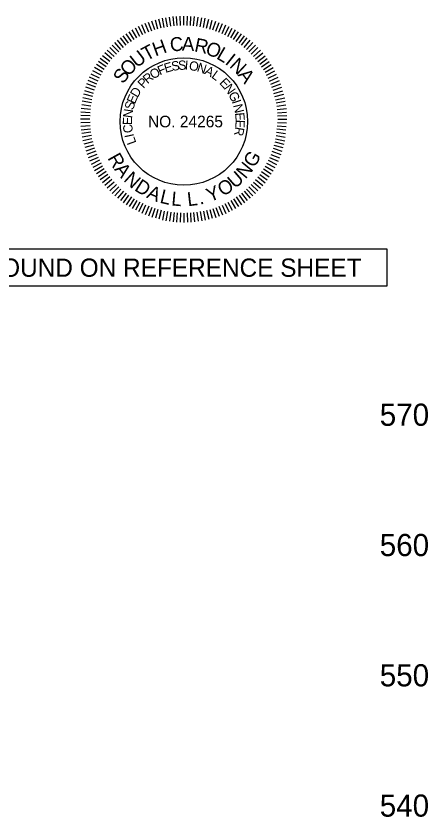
# Model space of a CAD drawing. Extents: x 1964849 to 1967422, y 1116563 to 1122210.
# Drawn here: x 1967263.8 to 1967421.9, y 1120325.5 to 1120632.8 of the extents above; entities that cross this region are included whole.
import ezdxf

# ---------------------------------------------------------------- set-up
doc = ezdxf.new("R2010")
doc.units = 0
for name, color, linetype in [('RD_DDB_Profile_Elev', 7, 'Continuous'), ('RD_Sketch1', 7, 'Continuous'), ('RD_TX_PEShield', 7, 'Continuous')]:
    doc.layers.add(name, color=color, linetype=linetype)

msp = doc.modelspace()

# ---------------------------------------------------------------- linework, layer by layer
at = {"layer": 'RD_Sketch1'}
msp.add_lwpolyline([(1967105.7, 1120543.48), (1967406.12, 1120543.48), (1967406.12, 1120529.22), (1967105.7, 1120529.22)], close=True, dxfattribs=at)
at = {"layer": 'RD_TX_PEShield'}
for p, q in [((1967324.46, 1120629.09), (1967324.09, 1120632.63)), ((1967324.46, 1120629.09), (1967324.09, 1120632.63)), ((1967325.71, 1120629.15), (1967325.47, 1120632.7)), ((1967325.71, 1120629.15), (1967325.47, 1120632.7)), ((1967326.97, 1120629.22), (1967326.84, 1120632.77)), ((1967326.97, 1120629.22), (1967326.84, 1120632.77)), ((1967328.23, 1120629.28), (1967328.23, 1120632.84)), ((1967328.23, 1120629.28), (1967328.23, 1120632.84)), ((1967329.48, 1120629.22), (1967329.61, 1120632.77)), ((1967329.48, 1120629.22), (1967329.61, 1120632.77)), ((1967330.74, 1120629.15), (1967330.98, 1120632.7)), ((1967330.74, 1120629.15), (1967330.98, 1120632.7)), ((1967331.99, 1120629.09), (1967332.36, 1120632.63)), ((1967331.99, 1120629.09), (1967332.36, 1120632.63)), ((1967314.74, 1120626.62), (1967313.41, 1120629.91)), ((1967314.74, 1120626.62), (1967313.41, 1120629.91)), ((1967315.91, 1120627.07), (1967314.7, 1120630.41)), ((1967315.91, 1120627.07), (1967314.7, 1120630.41)), ((1967317.09, 1120627.52), (1967315.99, 1120630.9)), ((1967317.09, 1120627.52), (1967315.99, 1120630.9)), ((1967318.3, 1120627.84), (1967317.32, 1120631.26)), ((1967318.3, 1120627.84), (1967317.32, 1120631.26)), ((1967319.52, 1120628.17), (1967318.66, 1120631.62)), ((1967319.52, 1120628.17), (1967318.66, 1120631.62)), ((1967320.73, 1120628.5), (1967319.99, 1120631.98)), ((1967320.73, 1120628.5), (1967319.99, 1120631.98)), ((1967321.97, 1120628.69), (1967321.36, 1120632.19)), ((1967321.97, 1120628.69), (1967321.36, 1120632.19)), ((1967323.21, 1120628.89), (1967322.72, 1120632.41)), ((1967323.21, 1120628.89), (1967322.72, 1120632.41)), ((1967333.24, 1120628.89), (1967333.73, 1120632.41)), ((1967333.24, 1120628.89), (1967333.73, 1120632.41)), ((1967334.48, 1120628.69), (1967335.09, 1120632.19)), ((1967334.48, 1120628.69), (1967335.09, 1120632.19)), ((1967335.72, 1120628.5), (1967336.46, 1120631.98)), ((1967335.72, 1120628.5), (1967336.46, 1120631.98)), ((1967335.72, 1120628.5), (1967336.46, 1120631.98)), ((1967336.93, 1120628.17), (1967337.79, 1120631.62)), ((1967336.93, 1120628.17), (1967337.79, 1120631.62)), ((1967336.93, 1120628.17), (1967337.79, 1120631.62)), ((1967338.15, 1120627.84), (1967339.13, 1120631.26)), ((1967338.15, 1120627.84), (1967339.13, 1120631.26)), ((1967338.15, 1120627.84), (1967339.13, 1120631.26)), ((1967339.36, 1120627.52), (1967340.46, 1120630.9)), ((1967339.36, 1120627.52), (1967340.46, 1120630.9)), ((1967339.36, 1120627.52), (1967340.46, 1120630.9)), ((1967340.54, 1120627.07), (1967341.75, 1120630.41)), ((1967340.54, 1120627.07), (1967341.75, 1120630.41)), ((1967340.54, 1120627.07), (1967341.75, 1120630.41)), ((1967341.71, 1120626.62), (1967343.04, 1120629.91)), ((1967341.71, 1120626.62), (1967343.04, 1120629.91)), ((1967341.71, 1120626.62), (1967343.04, 1120629.91)), ((1967309.15, 1120623.77), (1967307.26, 1120626.78)), ((1967309.15, 1120623.77), (1967307.26, 1120626.78)), ((1967310.2, 1120624.45), (1967308.42, 1120627.54)), ((1967310.2, 1120624.45), (1967308.42, 1120627.54)), ((1967311.32, 1120625.03), (1967309.65, 1120628.16)), ((1967311.32, 1120625.03), (1967309.65, 1120628.16)), ((1967312.44, 1120625.6), (1967310.88, 1120628.79)), ((1967312.44, 1120625.6), (1967310.88, 1120628.79)), ((1967313.56, 1120626.17), (1967312.12, 1120629.42)), ((1967313.56, 1120626.17), (1967312.12, 1120629.42)), ((1967342.89, 1120626.17), (1967344.33, 1120629.42)), ((1967342.89, 1120626.17), (1967344.33, 1120629.42)), ((1967342.89, 1120626.17), (1967344.33, 1120629.42)), ((1967344.01, 1120625.6), (1967345.57, 1120628.79)), ((1967344.01, 1120625.6), (1967345.57, 1120628.79)), ((1967344.01, 1120625.6), (1967345.57, 1120628.79)), ((1967345.13, 1120625.03), (1967346.8, 1120628.16)), ((1967345.13, 1120625.03), (1967346.8, 1120628.16)), ((1967345.13, 1120625.03), (1967346.8, 1120628.16)), ((1967346.25, 1120624.45), (1967348.03, 1120627.54)), ((1967346.25, 1120624.45), (1967348.03, 1120627.54)), ((1967346.25, 1120624.45), (1967348.03, 1120627.54)), ((1967347.3, 1120623.77), (1967349.19, 1120626.78)), ((1967347.3, 1120623.77), (1967349.19, 1120626.78)), ((1967347.3, 1120623.77), (1967349.19, 1120626.78)), ((1967305.08, 1120620.82), (1967302.8, 1120623.54)), ((1967305.08, 1120620.82), (1967302.8, 1120623.54)), ((1967306.06, 1120621.61), (1967303.87, 1120624.41)), ((1967306.06, 1120621.61), (1967303.87, 1120624.41)), ((1967307.04, 1120622.4), (1967304.95, 1120625.28)), ((1967307.04, 1120622.4), (1967304.95, 1120625.28)), ((1967308.09, 1120623.08), (1967306.11, 1120626.03)), ((1967308.09, 1120623.08), (1967306.11, 1120626.03)), ((1967348.36, 1120623.08), (1967350.34, 1120626.03)), ((1967348.36, 1120623.08), (1967350.34, 1120626.03)), ((1967348.36, 1120623.08), (1967350.34, 1120626.03)), ((1967349.41, 1120622.4), (1967351.5, 1120625.28)), ((1967349.41, 1120622.4), (1967351.5, 1120625.28)), ((1967349.41, 1120622.4), (1967351.5, 1120625.28)), ((1967350.39, 1120621.61), (1967352.58, 1120624.41)), ((1967350.39, 1120621.61), (1967352.58, 1120624.41)), ((1967350.39, 1120621.61), (1967352.58, 1120624.41)), ((1967351.37, 1120620.82), (1967353.65, 1120623.54)), ((1967351.37, 1120620.82), (1967353.65, 1120623.54)), ((1967351.37, 1120620.82), (1967353.65, 1120623.54)), ((1967302.33, 1120618.25), (1967299.77, 1120620.72)), ((1967302.33, 1120618.25), (1967299.77, 1120620.72)), ((1967303.22, 1120619.14), (1967300.75, 1120621.69)), ((1967303.22, 1120619.14), (1967300.75, 1120621.69)), ((1967304.11, 1120620.02), (1967301.72, 1120622.67)), ((1967304.11, 1120620.02), (1967301.72, 1120622.67)), ((1967352.34, 1120620.02), (1967354.73, 1120622.67)), ((1967352.34, 1120620.02), (1967354.73, 1120622.67)), ((1967352.34, 1120620.02), (1967354.73, 1120622.67)), ((1967353.23, 1120619.14), (1967355.7, 1120621.69)), ((1967353.23, 1120619.14), (1967355.7, 1120621.69)), ((1967353.23, 1120619.14), (1967355.7, 1120621.69)), ((1967354.12, 1120618.25), (1967356.68, 1120620.72)), ((1967354.12, 1120618.25), (1967356.68, 1120620.72)), ((1967354.12, 1120618.25), (1967356.68, 1120620.72)), ((1967299.86, 1120615.4), (1967297.05, 1120617.59)), ((1967299.86, 1120615.4), (1967297.05, 1120617.59)), ((1967300.65, 1120616.38), (1967297.92, 1120618.66)), ((1967300.65, 1120616.38), (1967297.92, 1120618.66)), ((1967301.44, 1120617.36), (1967298.79, 1120619.74)), ((1967301.44, 1120617.36), (1967298.79, 1120619.74)), ((1967355.01, 1120617.36), (1967357.66, 1120619.74)), ((1967355.01, 1120617.36), (1967357.66, 1120619.74)), ((1967355.01, 1120617.36), (1967357.66, 1120619.74)), ((1967355.8, 1120616.38), (1967358.53, 1120618.66)), ((1967355.8, 1120616.38), (1967358.53, 1120618.66)), ((1967355.8, 1120616.38), (1967358.53, 1120618.66)), ((1967356.59, 1120615.4), (1967359.4, 1120617.59)), ((1967356.59, 1120615.4), (1967359.4, 1120617.59)), ((1967356.59, 1120615.4), (1967359.4, 1120617.59)), ((1967297.69, 1120612.32), (1967294.68, 1120614.2)), ((1967297.69, 1120612.32), (1967294.68, 1120614.2)), ((1967298.38, 1120613.37), (1967295.43, 1120615.36)), ((1967298.38, 1120613.37), (1967295.43, 1120615.36)), ((1967299.06, 1120614.42), (1967296.18, 1120616.52)), ((1967299.06, 1120614.42), (1967296.18, 1120616.52)), ((1967357.39, 1120614.42), (1967360.27, 1120616.52)), ((1967357.39, 1120614.42), (1967360.27, 1120616.52)), ((1967357.39, 1120614.42), (1967360.27, 1120616.52)), ((1967358.07, 1120613.37), (1967361.02, 1120615.36)), ((1967358.07, 1120613.37), (1967361.02, 1120615.36)), ((1967358.07, 1120613.37), (1967361.02, 1120615.36)), ((1967358.76, 1120612.32), (1967361.77, 1120614.2)), ((1967358.76, 1120612.32), (1967361.77, 1120614.2)), ((1967358.76, 1120612.32), (1967361.77, 1120614.2)), ((1967296.44, 1120610.14), (1967293.3, 1120611.81)), ((1967296.44, 1120610.14), (1967293.3, 1120611.81)), ((1967297.01, 1120611.26), (1967293.93, 1120613.04)), ((1967297.01, 1120611.26), (1967293.93, 1120613.04)), ((1967359.44, 1120611.26), (1967362.52, 1120613.04)), ((1967359.44, 1120611.26), (1967362.52, 1120613.04)), ((1967359.44, 1120611.26), (1967362.52, 1120613.04)), ((1967360.01, 1120610.14), (1967363.15, 1120611.81)), ((1967360.01, 1120610.14), (1967363.15, 1120611.81)), ((1967360.01, 1120610.14), (1967363.15, 1120611.81)), ((1967294.85, 1120606.72), (1967291.55, 1120608.06)), ((1967294.85, 1120606.72), (1967291.55, 1120608.06)), ((1967295.3, 1120607.9), (1967292.04, 1120609.35)), ((1967295.3, 1120607.9), (1967292.04, 1120609.35)), ((1967295.87, 1120609.02), (1967292.67, 1120610.58)), ((1967295.87, 1120609.02), (1967292.67, 1120610.58)), ((1967360.58, 1120609.02), (1967363.78, 1120610.58)), ((1967360.58, 1120609.02), (1967363.78, 1120610.58)), ((1967360.58, 1120609.02), (1967363.78, 1120610.58)), ((1967361.15, 1120607.9), (1967364.41, 1120609.35)), ((1967361.15, 1120607.9), (1967364.41, 1120609.35)), ((1967361.15, 1120607.9), (1967364.41, 1120609.35)), ((1967361.6, 1120606.72), (1967364.9, 1120608.06)), ((1967361.6, 1120606.72), (1967364.9, 1120608.06)), ((1967361.6, 1120606.72), (1967364.9, 1120608.06)), ((1967293.94, 1120604.38), (1967290.56, 1120605.48)), ((1967293.94, 1120604.38), (1967290.56, 1120605.48)), ((1967294.4, 1120605.55), (1967291.05, 1120606.77)), ((1967294.4, 1120605.55), (1967291.05, 1120606.77)), ((1967362.06, 1120605.55), (1967365.4, 1120606.77)), ((1967362.06, 1120605.55), (1967365.4, 1120606.77)), ((1967362.06, 1120605.55), (1967365.4, 1120606.77)), ((1967362.51, 1120604.38), (1967365.89, 1120605.48)), ((1967362.51, 1120604.38), (1967365.89, 1120605.48)), ((1967362.51, 1120604.38), (1967365.89, 1120605.48)), ((1967293.29, 1120601.95), (1967289.84, 1120602.81)), ((1967293.29, 1120601.95), (1967289.84, 1120602.81)), ((1967293.62, 1120603.16), (1967290.2, 1120604.14)), ((1967293.62, 1120603.16), (1967290.2, 1120604.14)), ((1967362.83, 1120603.16), (1967366.25, 1120604.14)), ((1967362.83, 1120603.16), (1967366.25, 1120604.14)), ((1967362.83, 1120603.16), (1967366.25, 1120604.14)), ((1967363.16, 1120601.95), (1967366.61, 1120602.81)), ((1967363.16, 1120601.95), (1967366.61, 1120602.81)), ((1967363.16, 1120601.95), (1967366.61, 1120602.81)), ((1967292.57, 1120598.25), (1967289.05, 1120598.74)), ((1967292.57, 1120598.25), (1967289.05, 1120598.74)), ((1967292.77, 1120599.49), (1967289.27, 1120600.11)), ((1967292.77, 1120599.49), (1967289.27, 1120600.11)), ((1967292.97, 1120600.73), (1967289.49, 1120601.47)), ((1967292.97, 1120600.73), (1967289.49, 1120601.47)), ((1967363.48, 1120600.73), (1967366.96, 1120601.47)), ((1967363.48, 1120600.73), (1967366.96, 1120601.47)), ((1967363.48, 1120600.73), (1967366.96, 1120601.47)), ((1967363.68, 1120599.49), (1967367.18, 1120600.11)), ((1967363.68, 1120599.49), (1967367.18, 1120600.11)), ((1967363.68, 1120599.49), (1967367.18, 1120600.11)), ((1967363.88, 1120598.25), (1967367.4, 1120598.74)), ((1967363.88, 1120598.25), (1967367.4, 1120598.74)), ((1967363.88, 1120598.25), (1967367.4, 1120598.74)), ((1967292.31, 1120595.75), (1967288.76, 1120596)), ((1967292.31, 1120595.75), (1967288.76, 1120596)), ((1967292.38, 1120597.01), (1967288.84, 1120597.38)), ((1967292.38, 1120597.01), (1967288.84, 1120597.38)), ((1967364.07, 1120597.01), (1967367.61, 1120597.38)), ((1967364.07, 1120597.01), (1967367.61, 1120597.38)), ((1967364.07, 1120597.01), (1967367.61, 1120597.38)), ((1967364.14, 1120595.75), (1967367.69, 1120596)), ((1967364.14, 1120595.75), (1967367.69, 1120596)), ((1967364.14, 1120595.75), (1967367.69, 1120596)), ((1967292.18, 1120593.24), (1967288.62, 1120593.24)), ((1967292.18, 1120593.24), (1967288.62, 1120593.24)), ((1967292.25, 1120594.49), (1967288.69, 1120594.62)), ((1967292.25, 1120594.49), (1967288.69, 1120594.62)), ((1967364.2, 1120594.49), (1967367.76, 1120594.62)), ((1967364.2, 1120594.49), (1967367.76, 1120594.62)), ((1967364.2, 1120594.49), (1967367.76, 1120594.62)), ((1967364.27, 1120593.24), (1967367.83, 1120593.24)), ((1967364.27, 1120593.24), (1967367.83, 1120593.24)), ((1967364.27, 1120593.24), (1967367.83, 1120593.24)), ((1967292.25, 1120591.98), (1967288.69, 1120591.86)), ((1967292.25, 1120591.98), (1967288.69, 1120591.86)), ((1967292.31, 1120590.73), (1967288.76, 1120590.48)), ((1967292.31, 1120590.73), (1967288.76, 1120590.48)), ((1967292.38, 1120589.47), (1967288.84, 1120589.1)), ((1967292.38, 1120589.47), (1967288.84, 1120589.1)), ((1967363.88, 1120589.49), (1967367.4, 1120589.12)), ((1967363.88, 1120589.49), (1967367.4, 1120589.12)), ((1967364.01, 1120590.74), (1967367.54, 1120590.49)), ((1967364.01, 1120590.74), (1967367.54, 1120590.49)), ((1967364.14, 1120591.98), (1967367.69, 1120591.86)), ((1967364.14, 1120591.98), (1967367.69, 1120591.86)), ((1967292.57, 1120588.23), (1967289.05, 1120587.73)), ((1967292.57, 1120588.23), (1967289.05, 1120587.73)), ((1967292.77, 1120586.99), (1967289.27, 1120586.37)), ((1967292.77, 1120586.99), (1967289.27, 1120586.37)), ((1967363.61, 1120587), (1967367.11, 1120586.38)), ((1967363.61, 1120587), (1967367.11, 1120586.38)), ((1967363.75, 1120588.25), (1967367.25, 1120587.75)), ((1967363.75, 1120588.25), (1967367.25, 1120587.75)), ((1967292.97, 1120585.74), (1967289.49, 1120585)), ((1967292.97, 1120585.74), (1967289.49, 1120585)), ((1967293.29, 1120584.53), (1967289.84, 1120583.67)), ((1967293.29, 1120584.53), (1967289.84, 1120583.67)), ((1967363.16, 1120584.53), (1967366.61, 1120583.67)), ((1967363.16, 1120584.53), (1967366.61, 1120583.67)), ((1967363.48, 1120585.74), (1967366.96, 1120585)), ((1967363.48, 1120585.74), (1967366.96, 1120585)), ((1967293.62, 1120583.31), (1967290.2, 1120582.33)), ((1967293.62, 1120583.31), (1967290.2, 1120582.33)), ((1967293.94, 1120582.1), (1967290.56, 1120581)), ((1967294.4, 1120580.92), (1967291.05, 1120579.71)), ((1967294.4, 1120580.92), (1967291.05, 1120579.71)), ((1967362.06, 1120580.92), (1967365.4, 1120579.71)), ((1967362.06, 1120580.92), (1967365.4, 1120579.71)), ((1967362.51, 1120582.1), (1967365.89, 1120581)), ((1967362.51, 1120582.1), (1967365.89, 1120581)), ((1967362.83, 1120583.31), (1967366.25, 1120582.33)), ((1967362.83, 1120583.31), (1967366.25, 1120582.33)), ((1967294.85, 1120579.75), (1967291.55, 1120578.42)), ((1967294.85, 1120579.75), (1967291.55, 1120578.42)), ((1967295.3, 1120578.58), (1967292.04, 1120577.13)), ((1967295.3, 1120578.58), (1967292.04, 1120577.13)), ((1967295.87, 1120577.46), (1967292.67, 1120575.9)), ((1967295.87, 1120577.46), (1967292.67, 1120575.9)), ((1967360.58, 1120577.46), (1967363.78, 1120575.9)), ((1967360.58, 1120577.46), (1967363.78, 1120575.9)), ((1967361.15, 1120578.58), (1967364.41, 1120577.13)), ((1967361.15, 1120578.58), (1967364.41, 1120577.13)), ((1967361.6, 1120579.75), (1967364.9, 1120578.42)), ((1967361.6, 1120579.75), (1967364.9, 1120578.42)), ((1967296.44, 1120576.34), (1967293.3, 1120574.67)), ((1967296.44, 1120576.34), (1967293.3, 1120574.67)), ((1967297.01, 1120575.22), (1967293.93, 1120573.44)), ((1967297.01, 1120575.22), (1967293.93, 1120573.44)), ((1967297.69, 1120574.16), (1967294.68, 1120572.28)), ((1967297.69, 1120574.16), (1967294.68, 1120572.28)), ((1967358.76, 1120574.16), (1967361.77, 1120572.28)), ((1967358.76, 1120574.16), (1967361.77, 1120572.28)), ((1967359.44, 1120575.22), (1967362.52, 1120573.44)), ((1967359.44, 1120575.22), (1967362.52, 1120573.44)), ((1967360.01, 1120576.34), (1967363.15, 1120574.67)), ((1967360.01, 1120576.34), (1967363.15, 1120574.67)), ((1967298.38, 1120573.11), (1967295.43, 1120571.12)), ((1967298.38, 1120573.11), (1967295.43, 1120571.12)), ((1967299.06, 1120572.05), (1967296.18, 1120569.96)), ((1967299.06, 1120572.05), (1967296.18, 1120569.96)), ((1967299.86, 1120571.07), (1967297.05, 1120568.88)), ((1967299.86, 1120571.07), (1967297.05, 1120568.88)), ((1967356.59, 1120571.07), (1967359.4, 1120568.88)), ((1967356.59, 1120571.07), (1967359.4, 1120568.88)), ((1967357.39, 1120572.05), (1967360.27, 1120569.96)), ((1967357.39, 1120572.05), (1967360.27, 1120569.96)), ((1967358.07, 1120573.11), (1967361.02, 1120571.12)), ((1967358.07, 1120573.11), (1967361.02, 1120571.12)), ((1967300.65, 1120570.1), (1967297.92, 1120567.81)), ((1967300.65, 1120570.1), (1967297.92, 1120567.81)), ((1967301.44, 1120569.12), (1967298.79, 1120566.74)), ((1967301.44, 1120569.12), (1967298.79, 1120566.74)), ((1967302.33, 1120568.23), (1967299.77, 1120565.76)), ((1967302.33, 1120568.23), (1967299.77, 1120565.76)), ((1967354.12, 1120568.23), (1967356.68, 1120565.76)), ((1967354.12, 1120568.23), (1967356.68, 1120565.76)), ((1967355.01, 1120569.12), (1967357.66, 1120566.74)), ((1967355.01, 1120569.12), (1967357.66, 1120566.74)), ((1967355.8, 1120570.1), (1967358.53, 1120567.81)), ((1967355.8, 1120570.1), (1967358.53, 1120567.81)), ((1967303.22, 1120567.34), (1967300.75, 1120564.78)), ((1967303.22, 1120567.34), (1967300.75, 1120564.78)), ((1967304.11, 1120566.45), (1967301.72, 1120563.81)), ((1967304.11, 1120566.45), (1967301.72, 1120563.81)), ((1967305.08, 1120565.66), (1967302.8, 1120562.94)), ((1967305.08, 1120565.66), (1967302.8, 1120562.94)), ((1967351.37, 1120565.66), (1967353.65, 1120562.94)), ((1967351.37, 1120565.66), (1967353.65, 1120562.94)), ((1967352.34, 1120566.45), (1967354.73, 1120563.81)), ((1967353.23, 1120567.34), (1967355.7, 1120564.78)), ((1967353.23, 1120567.34), (1967355.7, 1120564.78)), ((1967306.06, 1120564.87), (1967303.87, 1120562.07)), ((1967306.06, 1120564.87), (1967303.87, 1120562.07)), ((1967307.04, 1120564.08), (1967304.95, 1120561.2)), ((1967307.04, 1120564.08), (1967304.95, 1120561.2)), ((1967308.09, 1120563.39), (1967306.11, 1120560.44)), ((1967308.09, 1120563.39), (1967306.11, 1120560.44)), ((1967309.15, 1120562.71), (1967307.26, 1120559.69)), ((1967309.15, 1120562.71), (1967307.26, 1120559.69)), ((1967310.2, 1120562.02), (1967308.42, 1120558.94)), ((1967310.2, 1120562.02), (1967308.42, 1120558.94)), ((1967346.25, 1120562.02), (1967348.03, 1120558.94)), ((1967346.25, 1120562.02), (1967348.03, 1120558.94)), ((1967347.3, 1120562.71), (1967349.19, 1120559.69)), ((1967347.3, 1120562.71), (1967349.19, 1120559.69)), ((1967348.36, 1120563.39), (1967350.34, 1120560.44)), ((1967348.36, 1120563.39), (1967350.34, 1120560.44)), ((1967349.41, 1120564.08), (1967351.5, 1120561.2)), ((1967349.41, 1120564.08), (1967351.5, 1120561.2)), ((1967350.39, 1120564.87), (1967352.58, 1120562.07)), ((1967350.39, 1120564.87), (1967352.58, 1120562.07)), ((1967311.32, 1120561.45), (1967309.65, 1120558.31)), ((1967311.32, 1120561.45), (1967309.65, 1120558.31)), ((1967312.44, 1120560.88), (1967310.88, 1120557.68)), ((1967312.44, 1120560.88), (1967310.88, 1120557.68)), ((1967313.56, 1120560.31), (1967312.12, 1120557.06)), ((1967313.56, 1120560.31), (1967312.12, 1120557.06)), ((1967314.74, 1120559.86), (1967313.41, 1120556.56)), ((1967314.74, 1120559.86), (1967313.41, 1120556.56)), ((1967315.91, 1120559.41), (1967314.7, 1120556.07)), ((1967315.91, 1120559.41), (1967314.7, 1120556.07)), ((1967317.09, 1120558.96), (1967315.99, 1120555.57)), ((1967317.09, 1120558.96), (1967315.99, 1120555.57)), ((1967339.36, 1120558.96), (1967340.46, 1120555.57)), ((1967339.36, 1120558.96), (1967340.46, 1120555.57)), ((1967340.54, 1120559.41), (1967341.75, 1120556.07)), ((1967340.54, 1120559.41), (1967341.75, 1120556.07)), ((1967341.71, 1120559.86), (1967343.04, 1120556.56)), ((1967341.71, 1120559.86), (1967343.04, 1120556.56)), ((1967342.89, 1120560.31), (1967344.33, 1120557.06)), ((1967342.89, 1120560.31), (1967344.33, 1120557.06)), ((1967344.01, 1120560.88), (1967345.57, 1120557.68)), ((1967344.01, 1120560.88), (1967345.57, 1120557.68)), ((1967345.13, 1120561.45), (1967346.8, 1120558.31)), ((1967345.13, 1120561.45), (1967346.8, 1120558.31)), ((1967318.3, 1120558.63), (1967317.32, 1120555.21)), ((1967318.3, 1120558.63), (1967317.32, 1120555.21)), ((1967319.52, 1120558.31), (1967318.66, 1120554.86)), ((1967319.52, 1120558.31), (1967318.66, 1120554.86)), ((1967320.73, 1120557.98), (1967319.99, 1120554.5)), ((1967320.73, 1120557.98), (1967319.99, 1120554.5)), ((1967321.97, 1120557.78), (1967321.36, 1120554.28)), ((1967321.97, 1120557.78), (1967321.36, 1120554.28)), ((1967323.21, 1120557.59), (1967322.72, 1120554.07)), ((1967323.21, 1120557.59), (1967322.72, 1120554.07)), ((1967324.46, 1120557.39), (1967324.09, 1120553.85)), ((1967324.46, 1120557.39), (1967324.09, 1120553.85)), ((1967325.71, 1120557.32), (1967325.47, 1120553.78)), ((1967325.71, 1120557.32), (1967325.47, 1120553.78)), ((1967326.97, 1120557.26), (1967326.84, 1120553.71)), ((1967326.97, 1120557.26), (1967326.84, 1120553.71)), ((1967328.23, 1120557.19), (1967328.23, 1120553.63)), ((1967328.23, 1120557.19), (1967328.23, 1120553.63)), ((1967329.48, 1120557.26), (1967329.61, 1120553.71)), ((1967329.48, 1120557.26), (1967329.61, 1120553.71)), ((1967330.74, 1120557.32), (1967330.98, 1120553.78)), ((1967330.74, 1120557.32), (1967330.98, 1120553.78)), ((1967331.99, 1120557.39), (1967332.36, 1120553.85)), ((1967331.99, 1120557.39), (1967332.36, 1120553.85)), ((1967333.24, 1120557.59), (1967333.73, 1120554.07)), ((1967333.24, 1120557.59), (1967333.73, 1120554.07)), ((1967334.48, 1120557.78), (1967335.09, 1120554.28)), ((1967334.48, 1120557.78), (1967335.09, 1120554.28)), ((1967335.72, 1120557.98), (1967336.46, 1120554.5)), ((1967335.72, 1120557.98), (1967336.46, 1120554.5)), ((1967336.93, 1120558.31), (1967337.79, 1120554.86)), ((1967336.93, 1120558.31), (1967337.79, 1120554.86)), ((1967338.15, 1120558.63), (1967339.13, 1120555.21)), ((1967338.15, 1120558.63), (1967339.13, 1120555.21))]:
    msp.add_line(p, q, dxfattribs=at)
msp.add_circle((1967328.23, 1120592.36), 24.48, dxfattribs=at)

# ---------------------------------------------------------------- texts
at = {"layer": 'RD_DDB_Profile_Elev'}
for s, p in [('570', (1967403.42, 1120475.58)), ('560', (1967403.42, 1120425.58)), ('550', (1967403.42, 1120375.58)), ('540', (1967403.42, 1120325.58))]:
    msp.add_text(s, height=8.5, dxfattribs=at).set_placement(p)
at = {"layer": 'RD_Sketch1'}
msp.add_text('ALIGNMENT CONTROL CAN BE FOUND ON REFERENCE SHEET', height=7, dxfattribs=at).set_placement((1967109.35, 1120532.77))
at = {"layer": 'RD_TX_PEShield'}
for s, height, rotation, p in [('H', 5.34, 19.9102, (1967317.32, 1120617.28)), ('C', 5.34, 6.8832, (1967323.22, 1120619.1)), ('A', 5.34, 357.9448, (1967327.43, 1120619.55)), ('R', 5.34, 348.267, (1967332.02, 1120619.3)), ('T', 5.34, 28.0947, (1967313.88, 1120615.48)), ('O', 5.34, 339.3286, (1967336.16, 1120618.38)), ('L', 5.34, 329.6507, (1967340.42, 1120616.68)), ('U', 5.34, 37.7726, (1967310.2, 1120612.74)), ('I', 5.34, 321.4663, (1967343.75, 1120614.69)), ('O', 5.34, 47.4504, (1967307.03, 1120609.42)), ('F', 3.56, 23.0853, (1967319.04, 1120610.02)), ('E', 3.56, 16.1843, (1967321.22, 1120610.99)), ('S', 3.56, 8.6909, (1967323.71, 1120611.75)), ('S', 3.56, 1.79, (1967326.08, 1120612.15)), ('I', 3.56, 354.889, (1967328.47, 1120612.26)), ('O', 3.56, 350.4045, (1967330.02, 1120612.18)), ('N', 3.56, 341.7029, (1967333, 1120611.68)), ('N', 5.34, 317.0007, (1967345.45, 1120613.42)), ('S', 5.34, 54.9027, (1967305, 1120606.52)), ('O', 3.56, 31.7869, (1967316.47, 1120608.42)), ('A', 3.56, 333.0013, (1967335.87, 1120610.74)), ('L', 3.56, 324.2997, (1967338.56, 1120609.37)), ('A', 5.34, 307.3229, (1967348.74, 1120610.22)), ('P', 3.56, 46.7912, (1967312.71, 1120604.83)), ('R', 3.56, 39.8902, (1967314.32, 1120606.61)), ('E', 3.56, 313.2251, (1967341.64, 1120607.07)), ('D', 3.56, 59.074, (1967310.41, 1120601.25)), ('N', 3.56, 305.7317, (1967343.44, 1120605.19)), ('E', 3.56, 66.5674, (1967309.41, 1120598.85)), ('G', 3.56, 297.0301, (1967345.21, 1120602.74)), ('S', 3.56, 73.4683, (1967308.76, 1120596.54)), ('I', 3.56, 288.3285, (1967346.58, 1120600.05)), ('N', 3.56, 283.8441, (1967347.13, 1120598.6)), ('N', 3.56, 82.17, (1967308.35, 1120593.55)), ('E', 3.56, 89.6633, (1967308.37, 1120590.95)), ('E', 3.56, 275.1424, (1967347.86, 1120595.66)), ('E', 3.56, 267.6491, (1967348.12, 1120593.08)), ('C', 3.56, 97.7667, (1967308.77, 1120588.16)), ('R', 3.56, 260.1557, (1967348.04, 1120590.47)), ('I', 3.56, 102.2511, (1967309.15, 1120586.65)), ('L', 3.56, 109.7445, (1967310.06, 1120584.21)), ('R', 5.34, 299.1493, (1967298.82, 1120578.39)), ('G', 5.34, 60.1113, (1967355.33, 1120574.34)), ('A', 5.34, 308.0877, (1967301.35, 1120573.99)), ('N', 5.34, 50.4335, (1967351.92, 1120570.04)), ('N', 5.34, 317.7655, (1967304.82, 1120569.73)), ('U', 5.34, 40.7556, (1967347.83, 1120566.37)), ('D', 5.34, 327.4433, (1967308.96, 1120566.12)), ('Y', 5.34, 21.4, (1967338.11, 1120561.34)), ('O', 5.34, 31.0778, (1967343.18, 1120563.44)), ('A', 5.34, 337.1212, (1967313.64, 1120563.25)), ('L', 5.34, 346.799, (1967318.75, 1120561.22)), ('L', 5.34, 354.9835, (1967323.28, 1120560.18)), ('L', 5.34, 6.5171, (1967329.81, 1120559.84)), ('.', 5.34, 14.7016, (1967334.42, 1120560.4))]:
    msp.add_text(s, height=height, rotation=rotation, dxfattribs=at).set_placement(p)
msp.add_text('NO. 24265', height=4.45, dxfattribs=at).set_placement((1967314.47, 1120590.13))

doc.saveas('drawing.dxf')
